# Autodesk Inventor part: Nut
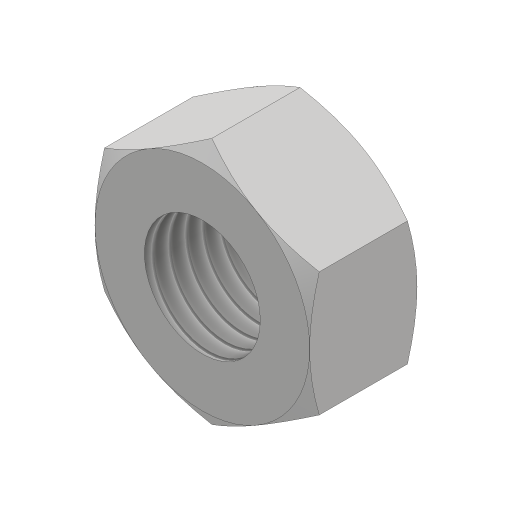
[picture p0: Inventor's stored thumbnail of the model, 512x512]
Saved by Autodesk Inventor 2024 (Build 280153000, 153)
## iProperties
Created: 2016-05
Part Number: Nut
Material: Generic
Document SubType Name: Modeling
Designer: CADCIM
Density: 1 g/cm^3
Appearance: Default
Author: CADCIM
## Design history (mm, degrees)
sketch "Sketch1"
  geometry: L1 (0, -18.475)-(-16, -9.238); L2 (-16, -9.238)-(-16, 9.238); L3 (-16, 9.238)-(0, 18.475); L4 (0, 18.475)-(16, 9.238); L5 (16, 9.238)-(16, -9.238); L6 (16, -9.238)-(0, -18.475); 2 further points
  constraints: 12 end point, 1 coincident, 13 other
  dimensions: "d0" = 32 distance between parallel lines of L2 L5
extrude "Extrusion1" new body sketch "Sketch1" distance "d1" = 16; taper "d2" = 0 deg
sketch "Sketch2"
  geometry: L1 (16, -9.238)-(16, 9.238) reference; C1 r 16 at (0, 0); 1 further point
  constraints: 1 centre point, 1 coincident, 1 tangent
extrude "Extrusion2" sketch "Sketch2" distance "d3" = 16; taper "d4" = 60 deg
sketch "Sketch3"
  geometry: L1 (0, -18.475)-(16, -9.238) reference; C1 r 16 at (0, 0); 1 further point
  constraints: 1 centre point, 1 coincident, 1 tangent
extrude "Extrusion3" sketch "Sketch3" distance "d5" = 16; taper "d6" = 60 deg
hole "Hole1" diameter "d9" = 17.294; stored, may be unused: countersink angle "d13" = 90 deg, drill point angle "d15" = 118 deg; dims "d7" = 10, "d8" = 10, "d10" = 40, "d11" = 4, "d12" = 2, "d14" = 51.2
body "Solid1"
